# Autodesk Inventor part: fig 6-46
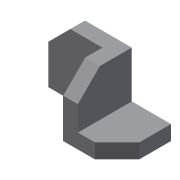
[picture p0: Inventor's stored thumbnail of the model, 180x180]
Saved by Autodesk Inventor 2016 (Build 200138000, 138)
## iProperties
Shininess: 77.0
Angle Display Precision: 2
Document Length Units: 11269
Document Angle Units: 11279
Document Time Units: 11290
Document Mass Units: 11283
Document Length Units Precision: 3
Document Angle Units Precision: 2
Created: 2001-12
Part Number: fig 6-46
Document SubType Name: Modeling
Designer: Renu Muthoo
Density: 1 g/cm^3
Material: Generic
Appearance: Default
Density: 0.0
Volumn: 0.0
Area: 0.0
PropertySet Name: Model Information
Control State: 0
Master: False
Checked Out: False
Author: Renu Muthoo
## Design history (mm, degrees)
node "Sketch1"
sketch "Sketch2"
  geometry: L1 (16.794, 27.142)-(16.794, -22.858); L2 (16.794, -22.858)-(-27.206, -22.858); L3 (-27.206, -22.858)-(-27.206, -10.858); L4 (-27.206, -10.858)-(4.794, -10.858); L5 (4.794, -10.858)-(4.794, 27.142); L6 (4.794, 27.142)-(16.794, 27.142)
  constraints: 12 end point, 4 parallel, 2 perpendicular, 1 vertical
  dimensions: "d0" = 44 distance of L1.end L2.end; "d1" = 50 distance of L1.start L1.end; "d2" = 12 distance of L2.end L3.end
extrude "Extrusion1" new body sketch "Sketch2" distance "d3" = 44; taper "d4" = 0 deg
sketch "Sketch4"
  geometry: L1 (-16.794, -27.142)-(-16.794, 22.858) reference; L2 (27.206, 22.858)-(27.206, 10.858) reference; L3 (-16.794, -27.142)-(-61.001, -27.142); L4 (-61.001, -27.142)-(-61.001, 22.858); L5 (-61.001, 22.858)-(-16.794, 22.858)
  constraints: 6 end point, 2 perpendicular, 1 parallel
extrude "Extrusion3" join sketch "Sketch4" distance "d13" = 12; taper "d14" = 0 deg
chamfer "Chamfer3" distance "d15" = 18; stored, may be unused: second distance "d16" = 2, angle "d17" = 45 deg
body "Solid1"
